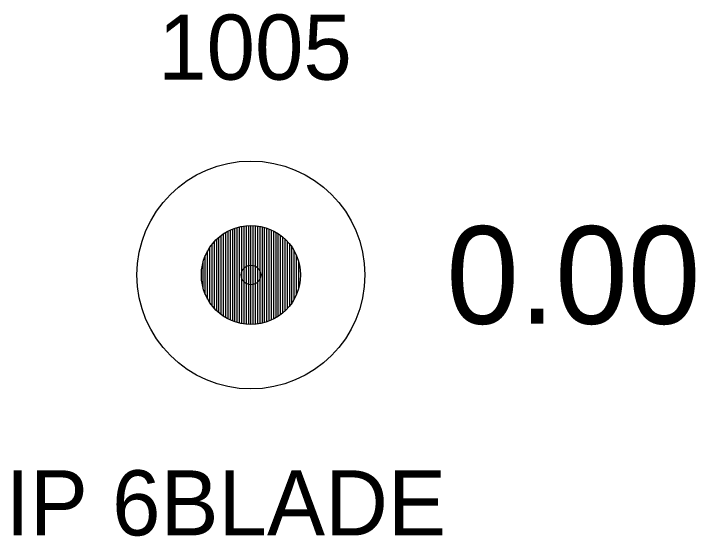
# Model space of a CAD drawing. Extents: x 2259948 to 2261336, y 1064647 to 1065986.
# Drawn here: x 2260558.85 to 2260569.32, y 1065977.7 to 1065985.73 of the extents above; entities that cross this region are included whole.
import ezdxf

# ---------------------------------------------------------------- set-up
doc = ezdxf.new("R2010")
doc.units = 0
for name, color, linetype in [('RD_EX_DV_Prop_txCode', 7, 'Continuous'), ('RD_EX_DV_PropPin', 7, 'Continuous'), ('RD_EX_TX_DV_Prop_ELEV', 7, 'Continuous'), ('RD_SMD_Locator', 7, 'Continuous')]:
    doc.layers.add(name, color=color, linetype=linetype)

msp = doc.modelspace()

# ---------------------------------------------------------------- linework, layer by layer
at = {"layer": 'RD_EX_DV_PropPin'}
for p, q in [((2260562.252, 1065980.992), (2260562.252, 1065982.433)), ((2260562.287, 1065980.981), (2260562.287, 1065982.444)), ((2260562.322, 1065980.972), (2260562.322, 1065982.453)), ((2260562.357, 1065980.965), (2260562.357, 1065982.461)), ((2260562.392, 1065980.959), (2260562.392, 1065982.466)), ((2260562.427, 1065980.955), (2260562.427, 1065982.47)), ((2260562.462, 1065980.952), (2260562.462, 1065982.473)), ((2260562.497, 1065980.952), (2260562.497, 1065982.474)), ((2260562.532, 1065980.952), (2260562.532, 1065982.473)), ((2260562.567, 1065980.955), (2260562.567, 1065982.47)), ((2260562.602, 1065980.959), (2260562.602, 1065982.466)), ((2260562.637, 1065980.965), (2260562.637, 1065982.461)), ((2260562.672, 1065980.972), (2260562.672, 1065982.453)), ((2260562.707, 1065980.981), (2260562.707, 1065982.444)), ((2260562.742, 1065980.992), (2260562.742, 1065982.433)), ((2260562.041, 1065981.103), (2260562.041, 1065982.322)), ((2260562.077, 1065981.078), (2260562.077, 1065982.347)), ((2260562.112, 1065981.056), (2260562.112, 1065982.369)), ((2260562.147, 1065981.037), (2260562.147, 1065982.388)), ((2260562.182, 1065981.02), (2260562.182, 1065982.405)), ((2260562.217, 1065981.005), (2260562.217, 1065982.42)), ((2260562.777, 1065981.005), (2260562.777, 1065982.42)), ((2260562.812, 1065981.02), (2260562.812, 1065982.405)), ((2260562.847, 1065981.037), (2260562.847, 1065982.388)), ((2260562.882, 1065981.056), (2260562.882, 1065982.369)), ((2260562.917, 1065981.078), (2260562.917, 1065982.347)), ((2260562.952, 1065981.103), (2260562.952, 1065982.322)), ((2260561.936, 1065981.198), (2260561.936, 1065982.228)), ((2260561.971, 1065981.162), (2260561.971, 1065982.263)), ((2260562.006, 1065981.13), (2260562.006, 1065982.295)), ((2260562.987, 1065981.13), (2260562.987, 1065982.295)), ((2260563.022, 1065981.162), (2260563.022, 1065982.263)), ((2260563.057, 1065981.198), (2260563.057, 1065982.228)), ((2260561.866, 1065981.286), (2260561.866, 1065982.139)), ((2260561.901, 1065981.238), (2260561.901, 1065982.187)), ((2260563.092, 1065981.238), (2260563.092, 1065982.187)), ((2260563.127, 1065981.286), (2260563.127, 1065982.139)), ((2260561.796, 1065981.415), (2260561.796, 1065982.011)), ((2260561.831, 1065981.343), (2260561.831, 1065982.082)), ((2260563.162, 1065981.343), (2260563.162, 1065982.082)), ((2260563.197, 1065981.415), (2260563.197, 1065982.011)), ((2260561.761, 1065981.516), (2260561.761, 1065981.909)), ((2260563.232, 1065981.516), (2260563.232, 1065981.909))]:
    msp.add_line(p, q, dxfattribs=at)
for radius in [1.75, 0.761]:
    msp.add_circle((2260562.497, 1065981.713), radius, dxfattribs=at)
at = {"layer": 'RD_SMD_Locator'}
msp.add_circle((2260562.497, 1065981.713), 0.15, dxfattribs=at)

# ---------------------------------------------------------------- texts
at = {"layer": 'RD_EX_DV_Prop_txCode'}
for s, p in [('1005', (2260561.072, 1065984.713)), ('IP 6BLADE', (2260558.729, 1065977.713))]:
    msp.add_text(s, height=1, dxfattribs=at).set_placement(p)
at = {"layer": 'RD_EX_TX_DV_Prop_ELEV'}
msp.add_text('0.00', height=1.5, dxfattribs=at).set_placement((2260565.497, 1065980.963))

doc.saveas('drawing.dxf')
